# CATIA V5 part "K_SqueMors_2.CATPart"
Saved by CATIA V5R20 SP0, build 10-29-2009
Part number: Squelette_mors_2
Publications: "Axe_pivot_mors_1'", "Axe_pivot_mors_2'"
Bounding box of the stored display mesh (mm): x -650.011 to -400.011, y 55 to 95, z -177.283 to -147.283
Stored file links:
  G:\Khaled_CFAO_2011\ST2M\ST2M_GR2\jcoetard\Khaled\CAD_CATIA\K_SqueMors_2.CATPart
  G:\Khaled_CFAO_2011\ST2M\ST2M_GR2\jcoetard\jcoetard\Maquette_jcoetard\Squelette_mors.CATPart
  G:\Khaled_CFAO_2011\ST2M\ST2M_GR2\jcoetard\Khaled\CAD_CATIA\K_Squelette.CATProduct
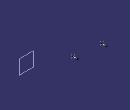
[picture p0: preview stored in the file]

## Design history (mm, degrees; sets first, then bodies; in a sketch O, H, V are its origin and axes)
Set1
  Point1 "Point.9": linked copy from another document
  Plane1 "Plan_Ref": linked copy from another document
  Point2 "Point.10": linked copy from another document
Set2 "Set géométrique"
  Line1 "Axe_pivot_mors_1'": type Normal, RefPoint Point1, RefSkin Plane1, Start 0, End 40
  Line2 "Axe_pivot_mors_2'": type Normal, RefPoint Point2, RefSkin Plane1, Start 0, End 40
Body1 (main body)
